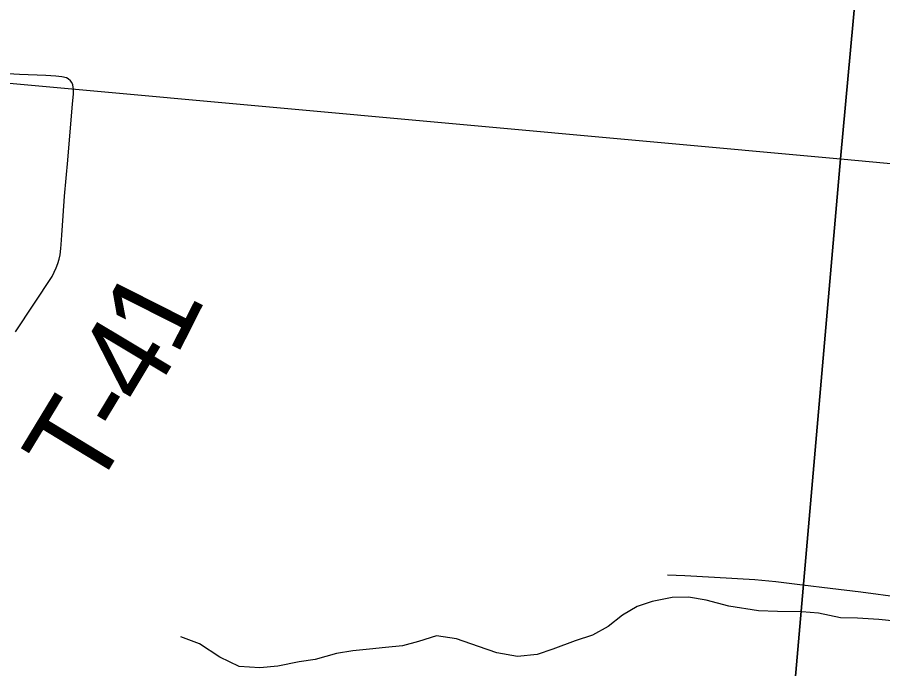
# Model space of a CAD drawing. Extents: x 0 to 34, y 0 to 22.
# Drawn here: x 6.814 to 7.382, y 19.835 to 20.263 of the extents above; entities that cross this region are included whole.
import ezdxf

# ---------------------------------------------------------------- set-up
doc = ezdxf.new("R2010")
doc.units = 0
for name, color, linetype in [('Default', 7, 'Continuous'), ('GM_X_Minor_River', 7, 'Continuous'), ('GM_X_Section', 7, 'Continuous'), ('GM_X_Township_Road', 7, 'Continuous'), ('GM_X_Township_Road_Text', 7, 'Continuous')]:
    doc.layers.add(name, color=color, linetype=linetype)

msp = doc.modelspace()

# ---------------------------------------------------------------- linework, layer by layer
at = {"layer": 'Default'}
for points in [[(7.42172, 20.89996), (6.3958, 20.89996), (6.34458, 20.2616), (7.35437, 20.16973)], [(8.43986, 20.89996), (7.42172, 20.89996), (7.35437, 20.16973), (8.36301, 20.07599)]]:
    msp.add_lwpolyline(points, close=True, dxfattribs=at)
at = {"layer": 'GM_X_Minor_River'}
msp.add_lwpolyline([(7.39026, 19.86613), (7.37967, 19.86735), (7.36568, 19.86821), (7.35434, 19.86829), (7.33998, 19.87144), (7.32902, 19.87228), (7.31313, 19.8724), (7.30066, 19.87287), (7.28101, 19.87605), (7.26628, 19.87996), (7.25457, 19.88194), (7.24398, 19.88164), (7.23072, 19.87908), (7.22086, 19.87574), (7.21136, 19.87012), (7.20184, 19.86261), (7.19159, 19.85699), (7.18021, 19.85328), (7.16541, 19.8477), (7.15518, 19.84436), (7.1423, 19.84294), (7.1287, 19.84532), (7.11663, 19.84958), (7.1023, 19.85462), (7.08907, 19.85662), (7.07731, 19.85291), (7.0667, 19.84996), (7.05572, 19.8489), (7.04512, 19.84784), (7.03414, 19.84678), (7.02354, 19.84496), (7.00951, 19.8409), (6.99891, 19.83946), (6.98489, 19.83653), (6.97315, 19.83548), (6.95954, 19.83634), (6.94673, 19.8425), (6.93355, 19.85133), (6.9211, 19.85597)], dxfattribs=at)
at = {"layer": 'GM_X_Section'}
for points in [[(7.35437, 20.16973), (7.26758, 19.17046), (6.2677, 19.26674), (6.34458, 20.2616)], [(8.36301, 20.07599), (8.27199, 19.07297), (7.26758, 19.17046), (7.35437, 20.16973)]]:
    msp.add_lwpolyline(points, close=True, dxfattribs=at)
at = {"layer": 'GM_X_Township_Road'}
for points in [[(6.81266, 20.05618), (6.83667, 20.09252), (6.83933, 20.09815), (6.84033, 20.10097), (6.84125, 20.10379), (6.84191, 20.10678), (6.84241, 20.11085), (6.84266, 20.1135), (6.84299, 20.11948), (6.84399, 20.13227), (6.84489, 20.14513), (6.84697, 20.16887), (6.85013, 20.20573), (6.85071, 20.21212), (6.85071, 20.21527), (6.85029, 20.21834), (6.84971, 20.21975), (6.8488, 20.221), (6.8473, 20.22221), (6.84606, 20.22291), (6.84307, 20.22349), (6.83917, 20.22391), (6.83261, 20.22432), (6.81535, 20.22507), (6.80389, 20.22573)], [(7.24076, 19.89663), (7.25215, 19.89605), (7.27177, 19.89498), (7.29808, 19.89346), (7.31194, 19.89217), (7.32956, 19.89005), (7.34766, 19.88784), (7.36773, 19.88547), (7.39375, 19.88201), (7.43115, 19.87784), (7.48605, 19.8715), (7.53521, 19.86523), (7.54214, 19.86433), (7.5481, 19.86341), (7.55436, 19.86218)]]:
    msp.add_lwpolyline(points, dxfattribs=at)

# ---------------------------------------------------------------- texts
at = {"layer": 'GM_X_Township_Road_Text'}
for s, rotation, p in [('1', 63.1772, (6.91828, 20.03924)), ('4', 59.0685, (6.89815, 20.00533)), ('-', 58.8036, (6.88592, 19.98512)), ('T', 58.7378, (6.86382, 19.94873))]:
    msp.add_text(s, height=0.05682, rotation=rotation, dxfattribs=at).set_placement(p)

doc.saveas('drawing.dxf')
